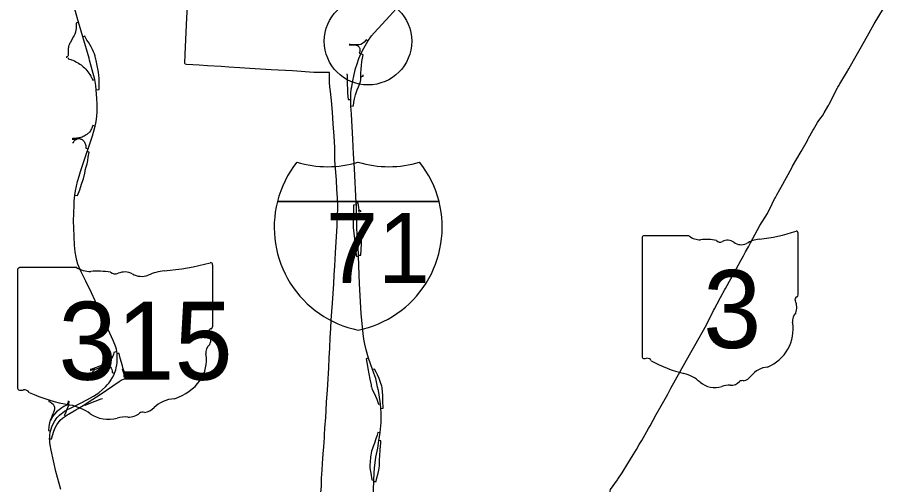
# Model space of a CAD drawing. Extents: x 0 to 34, y 0 to 22.
# Drawn here: x 5.166 to 6.606, y 18.155 to 18.927 of the extents above; entities that cross this region are included whole.
import ezdxf

# ---------------------------------------------------------------- set-up
doc = ezdxf.new("R2010")
doc.units = 0
for name, color, linetype in [('GM_X_Interchange_Ramps', 7, 'Continuous'), ('GM_X_Interstate_Route', 7, 'Continuous'), ('GM_X_Interstate_Shield', 7, 'Continuous'), ('GM_X_State_Route', 7, 'Continuous'), ('GM_X_State_Shield', 7, 'Continuous'), ('GM_X_US_Route', 7, 'Continuous'), ('SH_Text', 7, 'Continuous')]:
    doc.layers.add(name, color=color, linetype=linetype)

msp = doc.modelspace()

# ---------------------------------------------------------------- linework, layer by layer
at = {"layer": 'GM_X_Interchange_Ramps'}
for points in [[(5.267, 18.9187), (5.2628, 18.9175), (5.2629, 18.9141), (5.263, 18.9129), (5.263, 18.9116), (5.263, 18.9101), (5.2629, 18.9087), (5.2628, 18.9075), (5.2626, 18.9061), (5.2623, 18.9048), (5.262, 18.9034), (5.2616, 18.9022), (5.2611, 18.9006), (5.2606, 18.8993), (5.2602, 18.8982), (5.2595, 18.8968), (5.2588, 18.8955), (5.2529, 18.8849), (5.2522, 18.8837), (5.2517, 18.8826), (5.2512, 18.8815), (5.2508, 18.8804), (5.2504, 18.8791), (5.2502, 18.8778), (5.25, 18.8767), (5.2499, 18.8759), (5.2499, 18.8751), (5.2497, 18.867), (5.2497, 18.8652), (5.2495, 18.8637), (5.2491, 18.8629), (5.2485, 18.8621), (5.247, 18.8616), (5.247, 18.8602)], [(5.2947, 18.8595), (5.2944, 18.8628), (5.2932, 18.8667), (5.2918, 18.8701), (5.29, 18.874), (5.2877, 18.878), (5.2831, 18.8857), (5.2808, 18.8893), (5.2774, 18.8956), (5.2739, 18.8946)], [(5.7449, 18.8874), (5.7419, 18.8896), (5.7387, 18.8859), (5.7356, 18.8835), (5.7329, 18.8821), (5.7301, 18.8816), (5.7274, 18.8814), (5.7156, 18.882), (5.7136, 18.8821)], [(5.7136, 18.8814), (5.7154, 18.8813), (5.7256, 18.8808), (5.7283, 18.8798), (5.7301, 18.8776), (5.7312, 18.8755), (5.7316, 18.873), (5.7312, 18.8705), (5.7304, 18.8678), (5.7333, 18.8664)], [(5.2499, 18.8602), (5.2499, 18.8582), (5.2539, 18.8572), (5.2555, 18.8567), (5.2576, 18.8559), (5.26, 18.8549), (5.2626, 18.8536), (5.2647, 18.8525), (5.2669, 18.8512), (5.2691, 18.8498), (5.271, 18.8484), (5.2728, 18.847), (5.2747, 18.8454), (5.2768, 18.8434), (5.2787, 18.8414), (5.2807, 18.8392), (5.2823, 18.8371), (5.2841, 18.8347), (5.2855, 18.8325), (5.287, 18.8298), (5.2881, 18.8278), (5.2902, 18.8233), (5.2938, 18.8241)], [(5.2961, 18.8074), (5.3007, 18.8078), (5.3011, 18.8209), (5.301, 18.8265), (5.3006, 18.8309), (5.2997, 18.8366), (5.2989, 18.8419), (5.2958, 18.8557), (5.2953, 18.8576), (5.2947, 18.8595)], [(5.733, 18.8321), (5.7332, 18.8347), (5.7336, 18.8413), (5.7341, 18.8474), (5.7348, 18.854), (5.7358, 18.8595), (5.7369, 18.8648), (5.7333, 18.8664)], [(5.7102, 18.8335), (5.7106, 18.8309), (5.7103, 18.8235), (5.7103, 18.816), (5.7108, 18.8086), (5.7113, 18.8017), (5.7124, 18.7914), (5.7164, 18.7913)], [(5.7167, 18.7803), (5.7207, 18.7806), (5.7214, 18.7866), (5.7224, 18.7924), (5.7241, 18.7987), (5.7272, 18.8072), (5.7292, 18.8123), (5.7313, 18.8174), (5.7324, 18.8208), (5.7329, 18.8239), (5.7331, 18.8275), (5.7331, 18.8306), (5.733, 18.8321)], [(5.7331, 18.8275), (5.7334, 18.8275), (5.7338, 18.8285), (5.7345, 18.8291), (5.7352, 18.8295), (5.736, 18.8297), (5.7371, 18.8299), (5.7371, 18.832)], [(5.2942, 18.7474), (5.2906, 18.7481), (5.2895, 18.7455), (5.2889, 18.744), (5.2882, 18.7426), (5.2873, 18.741), (5.2865, 18.7396), (5.2849, 18.7373), (5.2834, 18.7358), (5.2822, 18.7348), (5.2808, 18.7336), (5.2794, 18.7326), (5.2778, 18.7316), (5.2762, 18.7307), (5.2745, 18.7299), (5.2728, 18.7291), (5.2709, 18.7285), (5.2692, 18.728), (5.2673, 18.7276), (5.2662, 18.7274), (5.2643, 18.7272), (5.2621, 18.727), (5.2598, 18.7269), (5.2574, 18.7268), (5.2564, 18.7264)], [(5.2565, 18.7254), (5.2579, 18.7254), (5.2614, 18.7256), (5.2649, 18.7265), (5.265, 18.7262)], [(5.2571, 18.7202), (5.2583, 18.7202), (5.2591, 18.7219), (5.2599, 18.723), (5.2608, 18.7239), (5.2618, 18.7247), (5.2627, 18.7253), (5.264, 18.7259), (5.265, 18.7262), (5.2654, 18.7263), (5.2667, 18.7265), (5.268, 18.7265), (5.2695, 18.7263), (5.2708, 18.7259), (5.2719, 18.7254), (5.2728, 18.7249), (5.2737, 18.7242), (5.2744, 18.7236), (5.275, 18.7228), (5.2759, 18.7218), (5.2767, 18.7206), (5.2775, 18.7192), (5.278, 18.718), (5.2785, 18.7166), (5.2788, 18.7152), (5.2791, 18.7136), (5.2791, 18.7109), (5.2826, 18.7097)], [(5.2776, 18.672), (5.278, 18.6747), (5.2797, 18.6801), (5.2811, 18.6851), (5.2822, 18.6905), (5.2829, 18.6958), (5.2842, 18.704), (5.281, 18.7051)], [(5.261, 18.6332), (5.2653, 18.6325), (5.2688, 18.6422), (5.272, 18.6515), (5.2741, 18.6572), (5.2748, 18.6604), (5.277, 18.6694), (5.2776, 18.672)], [(5.7257, 18.6171), (5.721, 18.6169), (5.7209, 18.6006), (5.7206, 18.5882), (5.7204, 18.582), (5.7205, 18.579)], [(5.7337, 18.6058), (5.7324, 18.6071), (5.7304, 18.6083), (5.73, 18.6126), (5.7288, 18.6201), (5.7255, 18.6199)], [(5.731, 18.6048), (5.7302, 18.6049), (5.7299, 18.6082), (5.7304, 18.6083)], [(5.7205, 18.579), (5.7207, 18.5755), (5.7237, 18.5513), (5.7255, 18.5347), (5.7258, 18.532), (5.7294, 18.5322)], [(5.7293, 18.5338), (5.7331, 18.5341), (5.734, 18.5525), (5.7348, 18.5682), (5.7347, 18.5725), (5.7342, 18.5758)], [(5.3303, 18.375), (5.3254, 18.3732), (5.3245, 18.3698), (5.3235, 18.367), (5.3221, 18.3642), (5.3205, 18.3619), (5.3183, 18.3593), (5.3162, 18.3572), (5.3136, 18.3554), (5.3107, 18.3542), (5.3077, 18.3528), (5.2874, 18.3452), (5.2862, 18.345)], [(5.348, 18.3326), (5.348, 18.3357), (5.3463, 18.3369), (5.3445, 18.3383), (5.3429, 18.3402), (5.3422, 18.3419), (5.3408, 18.3462), (5.3394, 18.3513), (5.3358, 18.364), (5.3339, 18.3715), (5.3307, 18.3714)], [(5.2872, 18.3398), (5.29, 18.3401), (5.2908, 18.3419), (5.2914, 18.3428), (5.2927, 18.3443), (5.2939, 18.345), (5.2964, 18.3463), (5.3096, 18.352), (5.3124, 18.3522), (5.3147, 18.3518), (5.3165, 18.3512), (5.3182, 18.35), (5.3195, 18.3489), (5.3209, 18.3471), (5.3221, 18.3449), (5.3225, 18.3431), (5.3226, 18.3408), (5.3225, 18.3402), (5.3265, 18.3393)], [(5.746, 18.364), (5.7418, 18.363), (5.7439, 18.3506), (5.7447, 18.3466), (5.748, 18.3294), (5.75, 18.3196), (5.7504, 18.3173)], [(5.2866, 18.3436), (5.2879, 18.344), (5.2936, 18.346), (5.2939, 18.345)], [(5.3424, 18.3324), (5.3424, 18.3346), (5.3422, 18.3368), (5.3419, 18.3389), (5.3413, 18.3408), (5.3397, 18.3458), (5.3408, 18.3462)], [(5.7681, 18.3155), (5.7677, 18.3177), (5.7658, 18.3239), (5.7635, 18.3301), (5.7605, 18.3366), (5.7583, 18.341), (5.7555, 18.3458), (5.7526, 18.3449)], [(5.2191, 18.2306), (5.2221, 18.2306), (5.226, 18.2433), (5.2284, 18.249), (5.2312, 18.2537), (5.2367, 18.2613), (5.2406, 18.265), (5.2454, 18.2683), (5.248, 18.27), (5.25, 18.2712), (5.2624, 18.2786), (5.2661, 18.2806), (5.2771, 18.2875), (5.2842, 18.2924), (5.3023, 18.3037), (5.3339, 18.3256), (5.3374, 18.3277), (5.341, 18.3293), (5.3436, 18.3301), (5.348, 18.331), (5.348, 18.3326)], [(5.7504, 18.3173), (5.7506, 18.3163), (5.752, 18.3123), (5.755, 18.3061), (5.7575, 18.3012), (5.7594, 18.2964), (5.7624, 18.2879), (5.7655, 18.2884)], [(5.7662, 18.2809), (5.7698, 18.2813), (5.7695, 18.2932), (5.7692, 18.3019), (5.7689, 18.309), (5.7682, 18.3136), (5.7681, 18.3155)], [(5.2179, 18.2955), (5.2178, 18.2923), (5.2199, 18.2916), (5.2225, 18.2898), (5.2248, 18.2878), (5.2261, 18.2856), (5.2271, 18.2829), (5.2271, 18.28), (5.2266, 18.2772), (5.2255, 18.2743), (5.224, 18.271), (5.2221, 18.2661), (5.2201, 18.2613), (5.2194, 18.2589), (5.219, 18.2571), (5.2178, 18.2511), (5.217, 18.2445), (5.2203, 18.2434)], [(5.2497, 18.2932), (5.2498, 18.2914), (5.2491, 18.2893), (5.2481, 18.2877), (5.2467, 18.2865), (5.2446, 18.2852), (5.2423, 18.2838), (5.2393, 18.282), (5.2346, 18.2787), (5.2306, 18.2752), (5.2271, 18.2715), (5.2245, 18.268), (5.2225, 18.2647), (5.2207, 18.261), (5.2201, 18.2613)], [(5.2454, 18.2683), (5.2437, 18.2697), (5.2459, 18.2734), (5.2477, 18.2785), (5.25, 18.2851), (5.2515, 18.2916), (5.2514, 18.2931)], [(5.2771, 18.2875), (5.2777, 18.2861), (5.2842, 18.289), (5.3042, 18.2965), (5.3063, 18.2975)], [(5.7649, 18.2407), (5.7612, 18.2412), (5.7599, 18.2367), (5.758, 18.2305), (5.7555, 18.2234), (5.7534, 18.2178), (5.7519, 18.2131), (5.7509, 18.2104), (5.7502, 18.2071), (5.7494, 18.2034), (5.7492, 18.2011)], [(5.7642, 18.2001), (5.7643, 18.2018), (5.7651, 18.2132), (5.766, 18.2237), (5.7663, 18.2271), (5.7626, 18.2278)], [(5.7492, 18.2011), (5.7491, 18.2), (5.7483, 18.1933), (5.748, 18.1867), (5.7482, 18.1832), (5.7487, 18.1793), (5.7496, 18.174), (5.7503, 18.1703), (5.7509, 18.1669), (5.7511, 18.1628), (5.7546, 18.1626)], [(5.7544, 18.1602), (5.7583, 18.1599), (5.7592, 18.1639), (5.7616, 18.174), (5.7627, 18.1786), (5.7633, 18.1823), (5.7639, 18.1866), (5.764, 18.1889), (5.7641, 18.1983), (5.7642, 18.2001)]]:
    msp.add_lwpolyline(points, dxfattribs=at)
at = {"layer": 'GM_X_Interstate_Route'}
for points in [[(5.7219, 18.8327), (5.7245, 18.8425), (5.727, 18.8502), (5.7299, 18.859), (5.7333, 18.8664), (5.7383, 18.8761), (5.7449, 18.8874), (5.7508, 18.8961), (5.7551, 18.9015), (5.7809, 18.9294), (5.8007, 18.9516), (5.8146, 18.9686), (5.8236, 18.9815), (5.8301, 18.993), (5.8386, 19.0115), (5.8443, 19.03), (5.8484, 19.0567), (5.85, 19.076)], [(5.7258, 18.6078), (5.7257, 18.6171), (5.7255, 18.6199), (5.7226, 18.677), (5.7208, 18.7014), (5.7197, 18.7257), (5.7174, 18.7667), (5.7167, 18.7803), (5.7164, 18.7913), (5.7165, 18.8009), (5.7172, 18.8081), (5.7183, 18.8119), (5.7193, 18.819), (5.7219, 18.8327)], [(5.7262, 18.5869), (5.7259, 18.5981), (5.7258, 18.6078)], [(5.7581, 18.2005), (5.7609, 18.2154), (5.7626, 18.2278), (5.7649, 18.2407), (5.7658, 18.247), (5.7661, 18.2515), (5.7665, 18.2584), (5.7666, 18.2641), (5.7666, 18.2743), (5.7662, 18.2809), (5.7655, 18.2884), (5.7635, 18.3034), (5.7623, 18.3102), (5.7608, 18.316), (5.7596, 18.3222), (5.7576, 18.3301), (5.7547, 18.3389), (5.7526, 18.3449), (5.746, 18.364), (5.742, 18.3776), (5.7397, 18.387), (5.7382, 18.3951), (5.7368, 18.4047), (5.7358, 18.4149), (5.7337, 18.4376), (5.7308, 18.4866), (5.7294, 18.5322), (5.7293, 18.5338), (5.7286, 18.5468), (5.7272, 18.5697), (5.7264, 18.5776), (5.7262, 18.5869)], [(5.7658, 18.0446), (5.7639, 18.0494), (5.7624, 18.0547), (5.7602, 18.0629), (5.7585, 18.0723), (5.7577, 18.0788), (5.7571, 18.0837), (5.7558, 18.0965), (5.7548, 18.1095), (5.7536, 18.135), (5.7544, 18.1602), (5.7546, 18.1626), (5.7549, 18.1738), (5.7555, 18.1824), (5.7581, 18.2005)]]:
    msp.add_lwpolyline(points, dxfattribs=at)
at = {"layer": 'GM_X_Interstate_Shield'}
for p, q in [((5.5952, 18.6226), (5.8623, 18.6226)), ((5.8623, 18.6226), (5.5952, 18.6226)), ((5.8623, 18.6226), (5.5952, 18.6226))]:
    msp.add_line(p, q, dxfattribs=at)
for centre, start, end in [((5.7635, 18.5801), 141.669, 165.8066), ((5.678, 18.8537), 253.0091, 286.9909), ((5.7795, 18.8537), 253.0091, 286.9909), ((5.694, 18.5801), 14.1934, 38.331), ((5.7635, 18.5801), 165.8066, 258.463), ((5.694, 18.5801), 281.537, 14.1934)]:
    msp.add_arc(centre, 0.1735, start, end, dxfattribs=at)
at = {"layer": 'GM_X_State_Route'}
for points in [[(5.2842, 18.8595), (5.2739, 18.8946), (5.267, 18.9187), (5.2568, 18.9541), (5.246, 18.9913), (5.2408, 19.0108), (5.2393, 19.0172), (5.2371, 19.0273), (5.2365, 19.0316)], [(6.5211, 18.8118), (6.5229, 18.8149), (6.5242, 18.8171), (6.5367, 18.8382), (6.5373, 18.8391), (6.5388, 18.8417), (6.5469, 18.8558), (6.5577, 18.8747), (6.5699, 18.8961), (6.5701, 18.8964), (6.5811, 18.9161), (6.5964, 18.9417), (6.6055, 18.9579), (6.6063, 18.9594)], [(5.2878, 18.8465), (5.2851, 18.8562), (5.2842, 18.8595)], [(5.2377, 18.1472), (5.2351, 18.1566), (5.2295, 18.1769), (5.2215, 18.2121), (5.2201, 18.2205), (5.2194, 18.2248), (5.2192, 18.2278), (5.2191, 18.2306), (5.2192, 18.2332), (5.2194, 18.2374), (5.2198, 18.2404), (5.2203, 18.2434), (5.2225, 18.2502), (5.2248, 18.2554), (5.2271, 18.2594), (5.23, 18.2638), (5.2316, 18.2659), (5.2354, 18.2698), (5.2386, 18.2723), (5.2404, 18.2738), (5.2438, 18.2762), (5.2477, 18.2785), (5.2558, 18.2826), (5.27, 18.2893), (5.2815, 18.2954), (5.2913, 18.301), (5.3003, 18.3067), (5.3066, 18.312), (5.3115, 18.3166), (5.3144, 18.3197), (5.3168, 18.3225), (5.3183, 18.3248), (5.3202, 18.3274), (5.3228, 18.3319), (5.3249, 18.3358), (5.3265, 18.3393), (5.3282, 18.3446), (5.3292, 18.3477), (5.3302, 18.353), (5.3307, 18.3564), (5.3309, 18.3605), (5.3309, 18.3652), (5.3307, 18.3698), (5.3307, 18.3714), (5.3303, 18.375), (5.3294, 18.3786), (5.3281, 18.3837), (5.3242, 18.3932), (5.3187, 18.4053), (5.3063, 18.4319), (5.2882, 18.4718), (5.2789, 18.491), (5.2712, 18.5064), (5.2659, 18.5191), (5.2641, 18.5254), (5.2628, 18.5307), (5.2614, 18.5396), (5.2602, 18.5506), (5.2589, 18.5791), (5.2587, 18.5904), (5.2595, 18.6165), (5.2598, 18.6233), (5.261, 18.6332), (5.2619, 18.6404), (5.2633, 18.6479), (5.2653, 18.6558), (5.268, 18.6648), (5.2703, 18.6722), (5.281, 18.7051), (5.2826, 18.7097), (5.2899, 18.7313), (5.2926, 18.7411), (5.2942, 18.7474), (5.2954, 18.7523), (5.2965, 18.7583), (5.2975, 18.7701), (5.2976, 18.783), (5.2973, 18.7931), (5.2967, 18.7998), (5.2961, 18.8074), (5.2955, 18.8143), (5.2938, 18.8241), (5.2895, 18.8404), (5.2878, 18.8465)], [(6.5067, 18.7837), (6.5202, 18.8103), (6.5211, 18.8118)], [(6.5056, 18.7815), (6.5067, 18.7837)], [(6.4928, 18.7607), (6.4953, 18.764), (6.4981, 18.7689)], [(6.4981, 18.7689), (6.5043, 18.7794)], [(6.5043, 18.7794), (6.5056, 18.7815)], [(6.4726, 18.7273), (6.4796, 18.7397), (6.4806, 18.7414), (6.4873, 18.7532), (6.4885, 18.7548)], [(6.4885, 18.7548), (6.4928, 18.7607)], [(6.427, 18.6464), (6.4447, 18.6785), (6.4461, 18.681), (6.4603, 18.7055), (6.4705, 18.7235), (6.4714, 18.7252)], [(6.4714, 18.7252), (6.4726, 18.7273)], [(6.42, 18.6335), (6.425, 18.6427), (6.427, 18.6464)], [(6.4131, 18.6206), (6.4168, 18.6276), (6.4177, 18.6292)], [(6.4177, 18.6292), (6.42, 18.6335)], [(6.4047, 18.603), (6.4047, 18.603), (6.4122, 18.619), (6.4131, 18.6206)], [(6.3731, 18.548), (6.3748, 18.5512), (6.3767, 18.5546), (6.3923, 18.5831), (6.4047, 18.603)], [(6.3379, 18.4839), (6.3418, 18.4911), (6.3461, 18.4988), (6.3608, 18.525), (6.3652, 18.5331), (6.3686, 18.5396), (6.3731, 18.548)], [(6.3344, 18.4774), (6.3352, 18.4789), (6.3379, 18.4839)], [(6.3217, 18.4538), (6.3273, 18.4643), (6.3344, 18.4774)], [(6.317, 18.4452), (6.3217, 18.4538)], [(6.2847, 18.3848), (6.3042, 18.4189), (6.3157, 18.4428), (6.317, 18.4452)], [(6.2453, 18.3142), (6.276, 18.3696), (6.2847, 18.3848)], [(6.2082, 18.2479), (6.2107, 18.2523), (6.221, 18.2706), (6.2293, 18.2853), (6.24, 18.3043), (6.2453, 18.3142)], [(6.1881, 18.2132), (6.1929, 18.2211), (6.1969, 18.2276), (6.2082, 18.2479)], [(6.1445, 18.1373), (6.1445, 18.1376), (6.1448, 18.1412), (6.145, 18.1446), (6.1452, 18.1471), (6.1569, 18.163), (6.1574, 18.1638), (6.1649, 18.1744), (6.1738, 18.1897), (6.1827, 18.2044), (6.1881, 18.2132)]]:
    msp.add_lwpolyline(points, dxfattribs=at)
at = {"layer": 'GM_X_State_Shield'}
for p, q in [((6.4552, 18.4683), (6.4552, 18.5706)), ((6.1975, 18.5624), (6.1975, 18.3668)), ((6.2755, 18.5657), (6.2, 18.5657)), ((5.1662, 18.51), (5.1662, 18.3144)), ((5.2638, 18.5134), (5.1694, 18.5134)), ((5.4884, 18.4159), (5.4884, 18.5182)), ((6.4551, 18.4683), (6.4552, 18.4683)), ((5.4883, 18.416), (5.4884, 18.4159))]:
    msp.add_line(p, q, dxfattribs=at)
for centre, radius, start, end in [((6.3634, 18.8324), 0.2733, 275.8445, 288.9065), ((6.4523, 18.571), 0.00287, 351.8621, 97.738), ((6.2004, 18.5628), 0.00299, 98.1301, 188.1301), ((6.2935, 18.5884), 0.029, 231.6195, 271.1119), ((6.3031, 18.4559), 0.104, 80.4867, 94.9883), ((6.3267, 18.5638), 0.00835, 219.7921, 297.1024), ((6.3389, 18.5412), 0.0174, 54.4667, 119.1411), ((6.3613, 18.5722), 0.0209, 233.8562, 294.8282), ((6.3982, 18.506), 0.055, 97.3462, 120.7689), ((6.4521, 18.4679), 0.00307, 289.6038, 7.7341), ((6.4545, 18.4607), 0.00444, 107.944, 210.337), ((6.4263, 18.4478), 0.0267, 340.033, 23.6496), ((6.4654, 18.4254), 0.0194, 136.8065, 186.9296), ((6.3787, 18.4124), 0.0684, 292.3089, 8.9858), ((6.2005, 18.3663), 0.00301, 171.9584, 258.3066), ((6.2009, 18.3864), 0.023, 267.339, 280.6039), ((6.2056, 18.3555), 0.00829, 29.7484, 93.2717), ((6.3102, 18.5312), 0.1973, 240.4129, 257.1985), ((6.2514, 18.2789), 0.0617, 47.1842, 75.836), ((6.4075, 18.3119), 0.0374, 94.4031, 142.5768), ((6.3182, 18.3545), 0.0392, 230.7004, 286.2918), ((6.3437, 18.3399), 0.0209, 268.777, 315.5493), ((6.3626, 18.3209), 0.00588, 65.7517, 132.6484), ((6.3601, 18.3478), 0.0221, 282.8732, 323.2771), ((6.3408, 18.2869), 0.0322, 85.6951, 111.2099)]:
    msp.add_arc(centre, radius, start, end, dxfattribs=at)
for centre, major_axis, start_param, end_param in [((5.1699, 18.5104), (0.00373, 0), 1.712693, 3.28349), ((5.2862, 18.5361), (0.0362, 0), 4.042523, 4.731795), ((5.3736, 18.78), (0.3416, 0), 4.814394, 5.042369), ((5.4848, 18.5187), (0.00359, 0), 6.141152, 7.989035), ((5.2982, 18.4036), (0.1299, 0), 1.404758, 1.657858), ((5.3277, 18.5115), (0.0104, 0), 3.836095, 5.185415), ((5.343, 18.4889), (0.0217, 0), 0.950623, 2.079405), ((5.3711, 18.5199), (0.0261, 0), 4.081561, 5.145723), ((5.4172, 18.4537), (0.0687, 0), 1.699011, 2.107814), ((5.4875, 18.4084), (0.00555, 0), 1.883978, 3.671073), ((5.4845, 18.4155), (0.00384, 0), 5.05454, 6.418171), ((5.4522, 18.3955), (0.0333, 0), 5.934695, 6.695948), ((5.5012, 18.3731), (0.0242, 0), 2.387724, 3.262537), ((5.3928, 18.3601), (0.0854, 0), 5.101752, 6.440018), ((5.17, 18.314), (0.00376, 0), 3.00124, 4.508301), ((5.1705, 18.334), (0.0287, 0), 4.665946, 4.897461), ((5.1764, 18.3032), (0.0104, 0), 0.519207, 1.627899), ((5.3072, 18.4789), (0.2467, 0), 4.195997, 4.488961), ((5.4288, 18.2595), (0.0468, 0), 1.647645, 2.488434), ((5.2337, 18.2266), (0.0772, 0), 0.823519, 1.323587), ((5.3695, 18.2955), (0.0276, 0), 4.937069, 5.64225), ((5.3171, 18.3022), (0.049, 0), 4.026481, 4.996735), ((5.3454, 18.2346), (0.0402, 0), 1.495662, 1.94098), ((5.349, 18.2875), (0.0261, 0), 4.691044, 5.507374), ((5.3726, 18.2686), (0.00735, 0), 1.147584, 2.315152)]:
    msp.add_ellipse(centre, major_axis=major_axis, ratio=0.8, start_param=start_param, end_param=end_param, dxfattribs=at)
at = {"layer": 'GM_X_US_Route'}
for points in [[(5.445, 18.8492), (5.4427, 18.8493), (5.4426, 18.8504), (5.4432, 18.8659), (5.4455, 18.9261), (5.446, 18.9352), (5.4462, 18.941), (5.4472, 18.9672), (5.4475, 18.9752), (5.4482, 18.9951), (5.4488, 19.0098), (5.449, 19.0154), (5.4493, 19.0242), (5.4493, 19.0251), (5.4498, 19.0326), (5.4508, 19.0503), (5.4508, 19.0504)], [(5.6593, 18.8359), (5.6555, 18.836), (5.62, 18.8383), (5.5848, 18.8402), (5.5495, 18.8425), (5.533, 18.8435), (5.5149, 18.8447), (5.5023, 18.8455), (5.4797, 18.847), (5.4662, 18.8478), (5.445, 18.8492)], [(5.6813, 18.8356), (5.6593, 18.8359)], [(5.6952, 18.6155), (5.6944, 18.6286), (5.6936, 18.6431), (5.6927, 18.658), (5.6927, 18.6584), (5.6917, 18.6707), (5.6902, 18.6908), (5.6901, 18.6914), (5.6901, 18.7119), (5.689, 18.7306), (5.6876, 18.7512), (5.6864, 18.7702), (5.6846, 18.7896), (5.6829, 18.8045), (5.682, 18.8119), (5.6815, 18.8195), (5.6813, 18.8356)], [(5.6938, 18.5817), (5.6939, 18.5844), (5.6953, 18.613), (5.6952, 18.6155), (5.6952, 18.6155)], [(5.6801, 18.3481), (5.6809, 18.3647), (5.6818, 18.3804), (5.6827, 18.398), (5.6833, 18.413), (5.6843, 18.4268), (5.6853, 18.4409), (5.6862, 18.455), (5.6873, 18.4709), (5.6883, 18.4864), (5.6892, 18.5013), (5.6901, 18.5156), (5.6915, 18.538), (5.6924, 18.5559), (5.6938, 18.5817)], [(5.6662, 18.1286), (5.6667, 18.1366), (5.6681, 18.1525), (5.6683, 18.1658), (5.6692, 18.1791), (5.6699, 18.1898), (5.6708, 18.206), (5.6719, 18.2174), (5.6728, 18.2327), (5.6731, 18.237), (5.6738, 18.248), (5.675, 18.2661), (5.6757, 18.2777), (5.6765, 18.291), (5.677, 18.2985), (5.6778, 18.3111), (5.6784, 18.3202), (5.6801, 18.3481)]]:
    msp.add_lwpolyline(points, dxfattribs=at)
at = {"layer": 'SH_Text'}
msp.add_circle((5.7449, 18.8874), 0.0722, dxfattribs=at)

# ---------------------------------------------------------------- texts
at = {"layer": 'GM_X_Interstate_Shield'}
msp.add_text('71', height=0.11569, dxfattribs=at).set_placement((5.6753, 18.4882))
at = {"layer": 'GM_X_State_Shield'}
for s, height, p in [('3', 0.1288, (6.2985, 18.3806)), ('315', 0.12885, (5.2338, 18.3282))]:
    msp.add_text(s, height=height, dxfattribs=at).set_placement(p)

doc.saveas('drawing.dxf')
